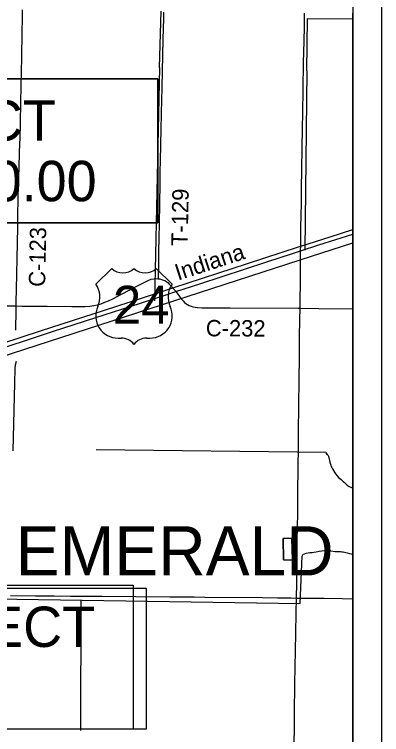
# Model space of a CAD drawing. Extents: x 0 to 64.8, y -5 to 22.
# Drawn here: x 7.727 to 9, y 17.279 to 19.777 of the extents above; entities that cross this region are included whole.
import ezdxf

# ---------------------------------------------------------------- set-up
doc = ezdxf.new("R2010")
doc.units = 0
for name, color, linetype in [('GM_X_Adjacent_County', 7, 'Continuous'), ('GM_X_County', 7, 'Continuous'), ('GM_X_County_Road', 7, 'Continuous'), ('GM_X_County_Road_Text', 7, 'Continuous'), ('GM_X_Minor_Lake', 7, 'Continuous'), ('GM_X_Minor_River', 7, 'Continuous'), ('GM_X_Rail_Line', 7, 'Continuous'), ('GM_X_Rail_Line_Text', 7, 'Continuous'), ('GM_X_Township', 7, 'Continuous'), ('GM_X_Township_Road', 7, 'Continuous'), ('GM_X_Township_Road_Text', 7, 'Continuous'), ('GM_X_Township_Text', 7, 'Continuous'), ('GM_X_US_Location', 7, 'Continuous'), ('GM_X_US_Route', 7, 'Continuous'), ('GM_X_US_Shield', 7, 'Continuous'), ('SH_Data', 7, 'Continuous'), ('SH_Masking', 7, 'Continuous'), ('SH_Text', 7, 'Continuous')]:
    doc.layers.add(name, color=color, linetype=linetype)

msp = doc.modelspace()

# ---------------------------------------------------------------- linework, layer by layer
at = {"layer": 'GM_X_Adjacent_County'}
msp.add_lwpolyline([(2.1, 19.9176), (2.1, 14.1), (8.9, 14.1), (8.9, 19.781)], dxfattribs=at)
at = {"layer": 'GM_X_County'}
msp.add_lwpolyline([(2.1, 19.9176), (2.1, 14.1), (8.9, 14.1), (8.9, 19.781)], dxfattribs=at)
at = {"layer": 'GM_X_County_Road'}
for points in [[(7.7335, 18.7658), (7.7336, 18.7807), (7.7343, 18.8243), (7.7365, 18.93), (7.7389, 19.0388), (7.7397, 19.0823), (7.742, 19.188), (7.7438, 19.244), (7.7451, 19.3), (7.7467, 19.3497), (7.748, 19.3963), (7.7501, 19.4772), (7.7506, 19.5238), (7.7513, 19.5767), (7.7525, 19.6295), (7.7543, 19.7135), (7.7549, 19.7663), (7.7554, 19.7881), (7.7556, 19.7928)], [(8.7196, 18.9731), (8.7199, 19.0035), (8.7204, 19.0377), (8.7212, 19.0812), (8.7219, 19.1216), (8.7225, 19.1713), (8.7262, 19.3827), (8.7267, 19.4355), (8.7283, 19.5163), (8.7299, 19.6096), (8.7313, 19.6841), (8.7325, 19.7339), (8.7329, 19.768), (8.7329, 19.7743), (8.733, 19.782)], [(8.7195, 18.9569), (8.7195, 18.96), (8.7196, 18.9731)], [(8.7173, 18.758), (8.7175, 18.7673), (8.7188, 18.8637), (8.7191, 18.8979), (8.7195, 18.9227), (8.7194, 18.9382), (8.7195, 18.9569)], [(7.7335, 18.7658), (7.7534, 18.7656), (7.8404, 18.7647), (7.9258, 18.7638), (7.9338, 18.7636), (7.955, 18.7635), (7.9718, 18.7642), (7.9892, 18.7657), (8.0028, 18.7676), (8.0156, 18.7704), (8.0276, 18.7738), (8.0412, 18.7785), (8.0533, 18.7835), (8.068, 18.7903), (8.0967, 18.8053), (8.1604, 18.8392), (8.1835, 18.8513), (8.1931, 18.8557), (8.2018, 18.8587), (8.2102, 18.8604), (8.2175, 18.8608), (8.2242, 18.8605), (8.227, 18.8601)], [(8.227, 18.8601), (8.2309, 18.8595), (8.2375, 18.858), (8.2445, 18.8556), (8.2506, 18.8527), (8.2558, 18.8495), (8.2601, 18.8462), (8.2631, 18.8432), (8.2717, 18.8333), (8.2738, 18.831), (8.2759, 18.8286)], [(8.2759, 18.8286), (8.2789, 18.8256), (8.2836, 18.8207), (8.2867, 18.8169), (8.2873, 18.8161)], [(8.2873, 18.8161), (8.2947, 18.8059), (8.3047, 18.7923), (8.3122, 18.7832), (8.3171, 18.7782), (8.3219, 18.7741), (8.3271, 18.7706), (8.3332, 18.7673), (8.3397, 18.7647), (8.3463, 18.7628), (8.3537, 18.7613), (8.3624, 18.7603), (8.3774, 18.7597), (8.4079, 18.7592), (8.4746, 18.759), (8.7109, 18.7581), (8.7173, 18.758)], [(6.7341, 18.7713), (6.8145, 18.7707), (6.8643, 18.7702), (6.8922, 18.7701), (6.9451, 18.7696), (7.0819, 18.7684), (7.1409, 18.7681), (7.2964, 18.7669), (7.3555, 18.7668), (7.4425, 18.7664), (7.486, 18.7663), (7.6384, 18.7662), (7.7254, 18.7659), (7.7335, 18.7658)], [(8.7047, 17.7527), (8.7047, 17.7541), (8.7058, 17.8038), (8.7071, 17.8846), (8.7078, 17.953), (8.7092, 18.0462), (8.71, 18.1239), (8.7115, 18.2793), (8.7119, 18.3384), (8.7127, 18.4099), (8.7142, 18.5218), (8.715, 18.5777), (8.7159, 18.6585), (8.7165, 18.7176), (8.7173, 18.758)], [(8.7173, 18.758), (8.7824, 18.7575), (8.9, 18.756)], [(8.6971, 17.2493), (8.6972, 17.2568), (8.6976, 17.2941), (8.6982, 17.3531), (8.6998, 17.4557), (8.7017, 17.5707), (8.7026, 17.6298), (8.7037, 17.7012), (8.7047, 17.7527)]]:
    msp.add_lwpolyline(points, dxfattribs=at)
at = {"layer": 'GM_X_Minor_Lake'}
for points in [[(8.6917, 17.8847), (8.6888, 17.9608), (8.6584, 17.9599)], [(8.6584, 17.9599), (8.6888, 17.9608), (8.6917, 17.8847), (8.6601, 17.885), (8.6584, 17.9599)], [(8.6584, 17.9599), (8.6601, 17.885), (8.6917, 17.8847)]]:
    msp.add_lwpolyline(points, dxfattribs=at)
at = {"layer": 'GM_X_Minor_River'}
for points in [[(8.2301, 19.593), (8.2362, 19.7887)], [(8.7412, 19.5813), (8.7429, 19.7629), (8.9, 19.7616)], [(8.2301, 19.593), (8.2127, 18.7837)], [(8.7412, 19.5813), (8.7345, 18.9593)], [(8.0106, 18.2685), (8.8062, 18.259)], [(8.8062, 18.259), (8.8113, 18.2502), (8.808, 18.2548), (8.8113, 18.2502), (8.8143, 18.2467), (8.8158, 18.2448), (8.8165, 18.2428), (8.8172, 18.2402), (8.8178, 18.2348), (8.8192, 18.2295), (8.8202, 18.2245), (8.8217, 18.2207), (8.8227, 18.2172), (8.8242, 18.2134), (8.8256, 18.2096), (8.8278, 18.2054), (8.83, 18.2007), (8.8329, 18.195), (8.8366, 18.1892), (8.8402, 18.1838), (8.8465, 18.1764), (8.851, 18.1714), (8.8554, 18.1671), (8.8596, 18.1636), (8.8633, 18.1601), (8.8674, 18.157), (8.8715, 18.1535), (8.876, 18.1492), (8.8812, 18.1445), (8.8872, 18.1402), (8.8936, 18.137), (8.9, 18.1336)], [(8.7242, 17.8985), (8.7283, 17.9052), (8.7329, 17.9066), (8.739, 17.9083), (8.7451, 17.9094), (8.7516, 17.9103), (8.7588, 17.9113), (8.7657, 17.9123), (8.7737, 17.9133), (8.7832, 17.9153), (8.7932, 17.9166), (8.8034, 17.9172), (8.8129, 17.9169), (8.8243, 17.9163), (8.8319, 17.9158), (8.8391, 17.9148), (8.846, 17.9147), (8.852, 17.9142), (8.8577, 17.914), (8.8623, 17.9136), (8.8668, 17.9131), (8.8714, 17.9122), (8.8759, 17.911), (8.8812, 17.9097), (8.8891, 17.9073), (8.8948, 17.9056), (8.9, 17.9039)], [(7.2048, 17.7571), (8.7176, 17.7337), (8.7242, 17.8985)], [(7.9574, 17.7454), (7.9567, 17.2934)]]:
    msp.add_lwpolyline(points, dxfattribs=at)
at = {"layer": 'GM_X_Rail_Line'}
msp.add_lwpolyline([(4.2913, 17.4823), (4.783, 17.6416), (5.7936, 17.9743), (6.8537, 18.3208), (7.9347, 18.672), (8.7178, 18.9261), (8.9, 18.9851)], dxfattribs=at)
at = {"layer": 'GM_X_Township'}
msp.add_lwpolyline([(5.5757, 14.1), (8.9, 14.1), (8.9, 19.781)], dxfattribs=at)
at = {"layer": 'GM_X_Township_Road'}
for points in [[(8.2375, 19.4363), (8.2394, 19.5237), (8.2431, 19.6914), (8.2449, 19.7628), (8.2455, 19.7783), (8.2458, 19.7854)], [(8.227, 18.8601), (8.2271, 18.8702), (8.2275, 18.9057), (8.2283, 18.9678), (8.2289, 18.9896), (8.2295, 19.0175), (8.2297, 19.0362), (8.2315, 19.1355), (8.2323, 19.1759), (8.2329, 19.2318), (8.2336, 19.2691), (8.2365, 19.3809), (8.2373, 19.4274), (8.2375, 19.4363)], [(7.7319, 18.6823), (7.7334, 18.7527), (7.7335, 18.7658)], [(7.7228, 18.263), (7.7285, 18.4978), (7.7294, 18.5495), (7.731, 18.5621), (7.7345, 18.5741)], [(7.7138, 17.7613), (7.8002, 17.7606), (7.8655, 17.7602), (7.9214, 17.7598), (7.9681, 17.7595), (8.0303, 17.7589), (8.2665, 17.7572), (8.3163, 17.7569), (8.3505, 17.7567), (8.3878, 17.7563), (8.5868, 17.7547), (8.6396, 17.754), (8.6645, 17.7536), (8.6862, 17.7531), (8.7047, 17.7527)], [(8.7047, 17.7527), (8.708, 17.7526), (8.7515, 17.7523), (8.8012, 17.7519), (8.8634, 17.751), (8.9, 17.7506)]]:
    msp.add_lwpolyline(points, dxfattribs=at)
at = {"layer": 'GM_X_US_Route'}
for points in [[(7.6333, 18.6031), (7.7592, 18.6441), (7.8597, 18.6769), (8.0424, 18.7364), (8.128, 18.7644), (8.2528, 18.8049), (8.2873, 18.8161), (8.3698, 18.8431), (8.6021, 18.9188), (8.6914, 18.9478), (8.7195, 18.9569), (8.783, 18.9776), (8.9, 19.0155)], [(7.6839, 18.6357), (7.8181, 18.6794), (8.0392, 18.7514), (8.2171, 18.8094), (8.2759, 18.8286), (8.5352, 18.913), (8.7125, 18.9708), (8.7196, 18.9731), (8.8213, 19.006), (8.9, 19.0316)]]:
    msp.add_lwpolyline(points, dxfattribs=at)
at = {"layer": 'GM_X_US_Shield'}
for p, q in [((8.0648, 18.8963), (8.0099, 18.8414)), ((8.2736, 18.8414), (8.2186, 18.8963)), ((8.0868, 18.6546), (8.0978, 18.6546)), ((8.1857, 18.6546), (8.1967, 18.6546))]:
    msp.add_line(p, q, dxfattribs=at)
for centre, radius, start, end in [((8.1033, 18.9355), 0.0549, 225.573, 314.427), ((8.1802, 18.9355), 0.0549, 225.573, 314.427), ((7.9469, 18.7973), 0.0769, 334.5471, 35.0009), ((8.3366, 18.7973), 0.0769, 144.9991, 205.4529), ((8.0859, 18.7315), 0.0769, 154.8319, 270.6383), ((8.1975, 18.7315), 0.0769, 269.3617, 25.1681), ((8.0978, 18.5997), 0.0549, 36.8699, 90), ((8.1857, 18.5997), 0.0549, 90, 143.1301)]:
    msp.add_arc(centre, radius, start, end, dxfattribs=at)
at = {"layer": 'SH_Data'}
for p, q in [((9, 21), (9, 14)), ((8.9, 20.9), (8.9, 14.1))]:
    msp.add_line(p, q, dxfattribs=at)
at = {"layer": 'SH_Masking'}
for points in [[(6.48, 19.5542), (8.2245, 19.5542), (8.2245, 19.0542), (6.48, 19.0542)], [(6.1118, 17.7975), (8.139, 17.7975), (8.139, 17.2975), (6.1118, 17.2975)], [(6.1118, 17.7875), (8.1844, 17.7875), (8.1844, 17.2975), (6.1118, 17.2975)]]:
    msp.add_lwpolyline(points, close=True, dxfattribs=at)
at = {"layer": 'SH_Text'}
for points in [[(6.48, 19.0542), (8.2245, 19.0542), (8.2245, 19.5542), (6.48, 19.5542)], [(6.1118, 17.7875), (8.1844, 17.7875), (8.1844, 17.2975), (6.1118, 17.2975)]]:
    msp.add_lwpolyline(points, close=True, dxfattribs=at)

# ---------------------------------------------------------------- texts
at = {"layer": 'GM_X_County_Road_Text'}
for s, rotation, p in [('C-123', 88.8986, (7.8338, 18.8319)), ('C-232', 359.7253, (8.3908, 18.6607))]:
    msp.add_text(s, height=0.05682, rotation=rotation, dxfattribs=at).set_placement(p)
at = {"layer": 'GM_X_Rail_Line_Text'}
msp.add_text('Indiana', height=0.05663, rotation=18.0002, dxfattribs=at).set_placement((8.2944, 18.8536))
at = {"layer": 'GM_X_Township_Road_Text'}
msp.add_text('T-129', height=0.05682, rotation=88.8765, dxfattribs=at).set_placement((8.3278, 18.9738))
at = {"layer": 'GM_X_Township_Text'}
msp.add_text('EMERALD', height=0.17045, rotation=0, dxfattribs=at).set_placement((7.732, 17.8313))
at = {"layer": 'GM_X_US_Location'}
for s in ['0', '/']:
    msp.add_text(s, height=0.000189, dxfattribs=at).set_placement((8.1417, 18.7689))
msp.add_text('24', height=0.000189, rotation=0, dxfattribs=at).set_placement((8.1026, 18.7297))
at = {"layer": 'GM_X_US_Shield'}
msp.add_text('24', height=0.13184, dxfattribs=at).set_placement((8.0688, 18.7041))
at = {"layer": 'SH_Text'}
for s, p in [('END PROJECT', (6.55, 19.3392)), ('STA. 1427+50.00', (6.55, 19.1292)), ('SUSPEND PROJECT', (6.1763, 17.5831))]:
    msp.add_text(s, height=0.14, dxfattribs=at).set_placement(p)

doc.saveas('drawing.dxf')
